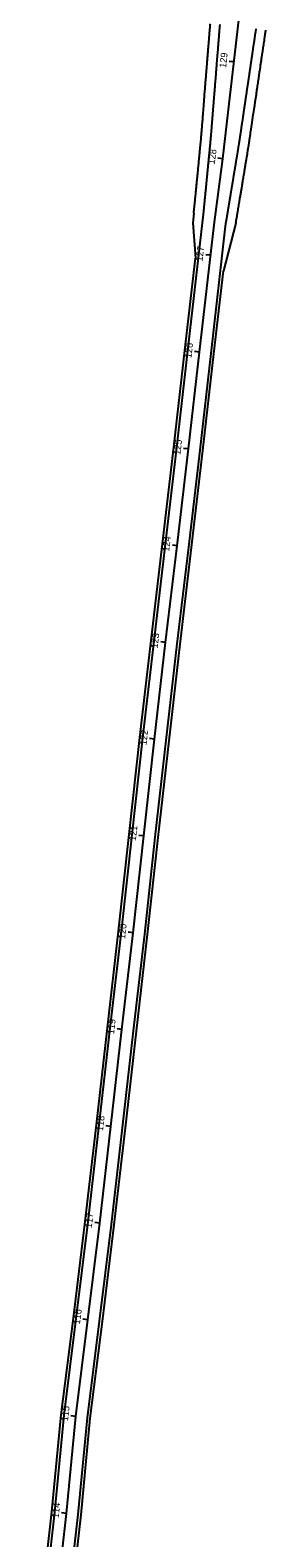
# Model space of a CAD drawing. Extents: x 2318076 to 2324211, y 613525 to 629939.
# Drawn here: x 2320288 to 2320529, y 625960 to 627508 of the extents above; entities that cross this region are included whole.
import ezdxf

# ---------------------------------------------------------------- set-up
doc = ezdxf.new("R2010")
doc.units = 0
for name, color, linetype in [('GE_P_CL_50', 7, 'Continuous'), ('PV_P_EOP', 7, 'Continuous'), ('PV_P_Shoulder', 7, 'Continuous')]:
    doc.layers.add(name, color=color, linetype=linetype)

msp = doc.modelspace()

# ---------------------------------------------------------------- linework, layer by layer
at = {"layer": 'GE_P_CL_50'}
for p, q in [((2320496.9, 627474.9), (2320491.9, 627475.5)), ((2320485.2, 627375.6), (2320480.3, 627376.2)), ((2320472.7, 627276.4), (2320467.7, 627276.9)), ((2320461.2, 627177), (2320456.3, 627177.6)), ((2320450, 627077.6), (2320445.1, 627078.2)), ((2320438.4, 626978.3), (2320433.5, 626978.9)), ((2320426.6, 626879), (2320421.7, 626879.6)), ((2320415.2, 626779.7), (2320410.2, 626780.2)), ((2320404.1, 626680.3), (2320399.2, 626680.9)), ((2320393.2, 626580.9), (2320388.2, 626581.4)), ((2320381.8, 626481.6), (2320376.8, 626482.2)), ((2320370.4, 626382.2), (2320365.4, 626382.8)), ((2320359, 626282.9), (2320354, 626283.4)), ((2320346.8, 626183.6), (2320341.8, 626184.2)), ((2320334.4, 626084.4), (2320329.5, 626085)), ((2320324.8, 625984.9), (2320319.9, 625985.4))]:
    msp.add_line(p, q, dxfattribs=at)
msp.add_lwpolyline([(2320302.5, 625786.1), (2320324.8, 625984.9), (2320334.4, 626084.4), (2320346.8, 626183.6), (2320359, 626282.9), (2320370.4, 626382.2), (2320381.8, 626481.6), (2320393.2, 626580.9), (2320404.1, 626680.3), (2320415.2, 626779.7), (2320426.6, 626879), (2320438.4, 626978.3), (2320450, 627077.6), (2320461.2, 627177), (2320476.3, 627307.7), (2320485.2, 627375.6), (2320502.1, 627520.9)], dxfattribs=at)
at = {"layer": 'PV_P_EOP'}
for points in [[(2320290.6, 625787.5), (2320312.9, 625986.1), (2320322.5, 626085.7), (2320334.9, 626185.1), (2320347, 626284.3), (2320358.5, 626383.6), (2320369.8, 626482.9), (2320381.3, 626582.2), (2320392.2, 626681.6), (2320403.3, 626781), (2320414.7, 626880.4), (2320426.5, 626979.7), (2320438.1, 627079), (2320449.3, 627178.4), (2320465.5, 627318.7)], [(2320314.4, 625784.8), (2320336.8, 625983.6), (2320346.4, 626083.1), (2320358.7, 626182.1), (2320370.9, 626281.4), (2320382.3, 626380.8), (2320393.7, 626480.2), (2320405.1, 626579.6), (2320416, 626679), (2320427.1, 626778.3), (2320438.5, 626877.6), (2320450.3, 626976.9), (2320462, 627076.3), (2320473.2, 627175.7), (2320488.2, 627306.2), (2320488.8, 627311)]]:
    msp.add_lwpolyline(points, dxfattribs=at)
for points in [[(2320477.1, 627446.7), (2320477.2, 627447.6), (2320477.3, 627448.5), (2320477.3, 627449.4), (2320477.4, 627450.3), (2320477.5, 627451.2), (2320477.5, 627452.1), (2320477.6, 627453), (2320477.7, 627453.9), (2320477.8, 627454.8), (2320477.8, 627455.7), (2320477.9, 627456.6), (2320478, 627457.5), (2320478, 627458.4), (2320478.1, 627459.3), (2320478.2, 627460.2), (2320478.3, 627461.1), (2320478.3, 627462), (2320478.4, 627462.9), (2320478.5, 627463.8), (2320478.5, 627464.7), (2320478.6, 627465.6), (2320478.7, 627466.5), (2320478.8, 627467.4), (2320478.8, 627468.3), (2320478.9, 627469.2), (2320479, 627470.1), (2320479.1, 627471), (2320479.1, 627471.9), (2320479.2, 627472.8), (2320479.3, 627473.7), (2320479.3, 627474.6), (2320479.4, 627475.5), (2320479.5, 627476.4), (2320479.6, 627477.3), (2320479.6, 627478.2), (2320479.7, 627479.1), (2320479.8, 627480), (2320479.8, 627480.9), (2320479.9, 627481.8), (2320480, 627482.7), (2320480.1, 627483.6), (2320480.1, 627484.5), (2320480.2, 627485.4), (2320480.3, 627486.3), (2320480.4, 627487.2), (2320480.4, 627488.1), (2320480.5, 627489), (2320480.6, 627489.9), (2320480.6, 627490.8), (2320480.7, 627491.7), (2320480.8, 627492.6), (2320480.9, 627493.5), (2320480.9, 627494.4), (2320481, 627495.3), (2320481.1, 627496.2), (2320481.1, 627497.1), (2320481.2, 627498), (2320481.3, 627498.9), (2320481.4, 627499.7), (2320481.4, 627500.6), (2320481.5, 627501.5), (2320481.6, 627502.4), (2320481.6, 627503.3), (2320481.7, 627504.2), (2320481.8, 627505.1), (2320481.9, 627506), (2320481.9, 627506.9), (2320482, 627507.8), (2320482.1, 627508.7), (2320482.2, 627509.6), (2320482.2, 627510.5), (2320482.3, 627511.4), (2320482.4, 627512.3), (2320482.4, 627513.2)], [(2320509.8, 627443), (2320509.9, 627443.9), (2320510, 627444.8), (2320510.2, 627445.7), (2320510.3, 627446.6), (2320510.4, 627447.5), (2320510.6, 627448.4), (2320510.7, 627449.3), (2320510.8, 627450.1), (2320511, 627451), (2320511.1, 627451.9), (2320511.2, 627452.8), (2320511.4, 627453.7), (2320511.5, 627454.6), (2320511.6, 627455.5), (2320511.8, 627456.4), (2320511.9, 627457.3), (2320512, 627458.2), (2320512.2, 627459.1), (2320512.3, 627460), (2320512.4, 627460.8), (2320512.6, 627461.7), (2320512.7, 627462.6), (2320512.8, 627463.5), (2320512.9, 627464.4), (2320513.1, 627465.3), (2320513.2, 627466.2), (2320513.3, 627467.1), (2320513.5, 627468), (2320513.6, 627468.9), (2320513.7, 627469.8), (2320513.9, 627470.7), (2320514, 627471.5), (2320514.1, 627472.4), (2320514.3, 627473.3), (2320514.4, 627474.2), (2320514.5, 627475.1), (2320514.7, 627476), (2320514.8, 627476.9), (2320514.9, 627477.8), (2320515.1, 627478.7), (2320515.2, 627479.6), (2320515.3, 627480.5), (2320515.5, 627481.4), (2320515.6, 627482.2), (2320515.7, 627483.1), (2320515.8, 627484), (2320516, 627484.9), (2320516.1, 627485.8), (2320516.2, 627486.7), (2320516.4, 627487.6), (2320516.5, 627488.5), (2320516.6, 627489.4), (2320516.8, 627490.3), (2320516.9, 627491.2), (2320517, 627492.1), (2320517.2, 627493), (2320517.3, 627493.8), (2320517.4, 627494.7), (2320517.6, 627495.6), (2320517.7, 627496.5), (2320517.8, 627497.4), (2320518, 627498.3), (2320518.1, 627499.2), (2320518.2, 627500.1), (2320518.4, 627501), (2320518.5, 627501.9), (2320518.6, 627502.8), (2320518.7, 627503.7), (2320518.9, 627504.5), (2320519, 627505.4), (2320519.1, 627506.3), (2320519.3, 627507.2), (2320519.4, 627508.1), (2320519.5, 627509)], [(2320471.5, 627380.5), (2320471.6, 627381.4), (2320471.7, 627382.3), (2320471.8, 627383.2), (2320471.9, 627384.1), (2320472, 627385), (2320472.1, 627385.9), (2320472.1, 627386.8), (2320472.2, 627387.7), (2320472.3, 627388.6), (2320472.4, 627389.5), (2320472.5, 627390.4), (2320472.6, 627391.3), (2320472.7, 627392.2), (2320472.8, 627393.1), (2320472.8, 627394), (2320472.9, 627394.9), (2320473, 627395.8), (2320473.1, 627396.4), (2320473.1, 627397.3), (2320473.2, 627398.2), (2320473.3, 627399.1), (2320473.4, 627400), (2320473.4, 627400.9), (2320473.5, 627401.8), (2320473.6, 627402.7), (2320473.6, 627403.6), (2320473.7, 627404.5), (2320473.8, 627405.4), (2320473.9, 627406.3), (2320473.9, 627407.2), (2320474, 627408.1), (2320474.1, 627409), (2320474.1, 627409.9), (2320474.2, 627410.8), (2320474.3, 627411.7), (2320474.4, 627412.6), (2320474.4, 627413.5), (2320474.5, 627414.4), (2320474.6, 627415.3), (2320474.7, 627416.2), (2320474.7, 627417.1), (2320474.8, 627418), (2320474.9, 627418.9), (2320474.9, 627419.8), (2320475, 627420.7), (2320475.1, 627421.6), (2320475.2, 627422.5), (2320475.2, 627423.4), (2320475.3, 627424.3), (2320475.4, 627425.2), (2320475.4, 627426.1), (2320475.5, 627427), (2320475.6, 627427.9), (2320475.7, 627428.8), (2320475.7, 627429.7), (2320475.8, 627430.6), (2320475.9, 627431.5), (2320476, 627432.4), (2320476, 627433.3), (2320476.1, 627434.2), (2320476.2, 627435.1), (2320476.2, 627436), (2320476.3, 627436.9), (2320476.4, 627437.8), (2320476.5, 627438.6), (2320476.5, 627439.5), (2320476.6, 627440.4), (2320476.7, 627441.3), (2320476.7, 627442.2), (2320476.8, 627443.1), (2320476.9, 627444), (2320477, 627444.9), (2320477, 627445.8), (2320477.1, 627446.7)], [(2320499.7, 627376.8), (2320499.9, 627377.7), (2320500, 627378.6), (2320500.2, 627379.5), (2320500.3, 627380.4), (2320500.5, 627381.3), (2320500.6, 627382.2), (2320500.8, 627383), (2320500.9, 627383.9), (2320501.1, 627384.8), (2320501.2, 627385.7), (2320501.3, 627386.6), (2320501.5, 627387.5), (2320501.6, 627388.4), (2320501.8, 627389.3), (2320501.9, 627390.2), (2320502.1, 627391), (2320502.2, 627391.9), (2320502.4, 627393.1), (2320502.5, 627394), (2320502.7, 627394.9), (2320502.8, 627395.8), (2320502.9, 627396.6), (2320503.1, 627397.5), (2320503.2, 627398.4), (2320503.3, 627399.3), (2320503.5, 627400.2), (2320503.6, 627401.1), (2320503.7, 627402), (2320503.9, 627402.9), (2320504, 627403.8), (2320504.1, 627404.7), (2320504.2, 627405.6), (2320504.4, 627406.5), (2320504.5, 627407.3), (2320504.6, 627408.2), (2320504.8, 627409.1), (2320504.9, 627410), (2320505, 627410.9), (2320505.2, 627411.8), (2320505.3, 627412.7), (2320505.4, 627413.6), (2320505.6, 627414.5), (2320505.7, 627415.4), (2320505.8, 627416.3), (2320506, 627417.2), (2320506.1, 627418), (2320506.2, 627418.9), (2320506.4, 627419.8), (2320506.5, 627420.7), (2320506.6, 627421.6), (2320506.8, 627422.5), (2320506.9, 627423.4), (2320507, 627424.3), (2320507.1, 627425.2), (2320507.3, 627426.1), (2320507.4, 627427), (2320507.5, 627427.9), (2320507.7, 627428.7), (2320507.8, 627429.6), (2320507.9, 627430.5), (2320508.1, 627431.4), (2320508.2, 627432.3), (2320508.3, 627433.2), (2320508.5, 627434.1), (2320508.6, 627435), (2320508.7, 627435.9), (2320508.9, 627436.8), (2320509, 627437.7), (2320509.1, 627438.6), (2320509.3, 627439.4), (2320509.4, 627440.3), (2320509.5, 627441.2), (2320509.7, 627442.1), (2320509.8, 627443)]]:
    msp.add_spline(points, degree=3, dxfattribs=at)
for points in [[(2320465.5, 627318.7), (2320465.5, 627319), (2320465.5, 627319.3), (2320465.6, 627319.5), (2320465.6, 627319.8), (2320465.6, 627320.1), (2320465.7, 627320.4), (2320465.7, 627320.7), (2320465.7, 627321), (2320465.7, 627321.3), (2320465.8, 627321.6), (2320465.8, 627321.9), (2320465.8, 627322.2), (2320465.9, 627322.5), (2320465.9, 627322.8), (2320465.9, 627323.1), (2320465.9, 627323.4), (2320466, 627323.7), (2320466, 627324), (2320466, 627324.3), (2320466.1, 627324.6), (2320466.1, 627324.9), (2320466.1, 627325.2), (2320466.2, 627325.5), (2320466.2, 627325.8), (2320466.2, 627326.1), (2320466.2, 627326.4), (2320466.3, 627326.7), (2320466.3, 627327), (2320466.3, 627327.3), (2320466.4, 627327.6), (2320466.4, 627327.9), (2320466.4, 627328.2), (2320466.4, 627328.5), (2320466.5, 627328.8), (2320466.5, 627329.1), (2320466.5, 627329.4), (2320466.6, 627329.7), (2320466.6, 627330), (2320466.6, 627330.3), (2320466.6, 627330.6), (2320466.7, 627330.9), (2320466.7, 627331.2), (2320466.7, 627331.5), (2320466.8, 627331.8), (2320466.8, 627332.1), (2320466.8, 627332.4), (2320466.9, 627332.7), (2320466.9, 627333), (2320466.9, 627333.3), (2320466.9, 627333.6), (2320467, 627333.9), (2320467, 627334.2), (2320467, 627334.5), (2320467.1, 627334.8), (2320467.1, 627335.1), (2320467.1, 627335.4), (2320467.1, 627335.7), (2320467.2, 627336), (2320467.2, 627336.3), (2320467.2, 627336.6), (2320467.3, 627336.9), (2320467.3, 627337.2), (2320467.3, 627337.5), (2320467.4, 627337.8), (2320467.4, 627338.1), (2320467.4, 627338.4), (2320467.4, 627338.7), (2320467.5, 627339), (2320467.5, 627339.3), (2320467.5, 627339.6), (2320467.6, 627339.9), (2320467.6, 627340.2), (2320467.6, 627340.5), (2320467.6, 627340.8), (2320467.7, 627341.1), (2320467.7, 627341.3), (2320467.7, 627341.6), (2320467.8, 627341.9), (2320467.8, 627342.2), (2320467.8, 627342.5), (2320467.8, 627342.8), (2320467.9, 627343.1), (2320467.9, 627343.4), (2320467.9, 627343.7), (2320468, 627344), (2320468, 627344.3), (2320468, 627344.6), (2320468.1, 627344.9), (2320468.1, 627345.2), (2320468.1, 627345.5), (2320468.1, 627345.8), (2320468.2, 627346.1), (2320468.2, 627346.4), (2320468.2, 627346.7), (2320468.3, 627347), (2320468.3, 627347.3), (2320468.3, 627347.6), (2320468.3, 627347.9), (2320468.4, 627348.2), (2320468.4, 627348.5), (2320468.4, 627348.8), (2320468.5, 627349.1), (2320468.5, 627349.4), (2320468.5, 627349.7), (2320468.5, 627350), (2320468.6, 627350.3), (2320468.6, 627350.6), (2320468.6, 627350.9), (2320468.7, 627351.2), (2320468.7, 627351.5), (2320468.7, 627351.8), (2320468.8, 627352.1), (2320468.8, 627352.4), (2320468.8, 627352.7), (2320468.8, 627353), (2320468.9, 627353.3), (2320468.9, 627353.6), (2320468.9, 627353.9), (2320469, 627354.2), (2320469, 627354.5), (2320469, 627354.8), (2320469, 627355.1), (2320469.1, 627355.4), (2320469.1, 627355.7), (2320469.1, 627356), (2320469.2, 627356.3), (2320469.2, 627356.6), (2320469.2, 627356.9), (2320469.2, 627357.2), (2320469.3, 627357.5), (2320469.3, 627357.8), (2320469.3, 627358.1), (2320469.4, 627358.4), (2320469.4, 627358.7), (2320469.4, 627359), (2320469.5, 627359.3), (2320469.5, 627359.6), (2320469.5, 627359.9), (2320469.5, 627360.2), (2320469.6, 627360.5), (2320469.6, 627360.8), (2320469.6, 627361.1), (2320469.7, 627361.4), (2320469.7, 627361.7), (2320469.7, 627362), (2320469.7, 627362.3), (2320469.8, 627362.6), (2320469.8, 627362.9), (2320469.8, 627363.2), (2320469.9, 627363.5), (2320469.9, 627363.8), (2320469.9, 627364.1), (2320470, 627364.4), (2320470, 627364.7), (2320470, 627365), (2320470, 627365.3), (2320470.1, 627365.6), (2320470.1, 627365.9), (2320470.1, 627366.2), (2320470.2, 627366.5), (2320470.2, 627366.8), (2320470.2, 627367.1), (2320470.2, 627367.4), (2320470.3, 627367.7), (2320470.3, 627368), (2320470.3, 627368.3), (2320470.4, 627368.6), (2320470.4, 627368.9), (2320470.4, 627369.2), (2320470.4, 627369.5), (2320470.5, 627369.8), (2320470.5, 627370.1), (2320470.5, 627370.4), (2320470.6, 627370.7), (2320470.6, 627371), (2320470.6, 627371.3), (2320470.7, 627371.6), (2320470.7, 627371.9), (2320470.7, 627372.2), (2320470.7, 627372.4), (2320470.8, 627372.7), (2320470.8, 627373), (2320470.8, 627373.3), (2320470.9, 627373.6), (2320470.9, 627373.9), (2320470.9, 627374.2), (2320470.9, 627374.5), (2320471, 627374.8), (2320471, 627375.1), (2320471, 627375.4), (2320471.1, 627375.7), (2320471.1, 627376), (2320471.1, 627376.3), (2320471.1, 627376.6), (2320471.2, 627376.9), (2320471.2, 627377.2), (2320471.2, 627377.5), (2320471.3, 627377.8), (2320471.3, 627378.1), (2320471.3, 627378.4), (2320471.4, 627378.7), (2320471.4, 627379), (2320471.4, 627379.3), (2320471.4, 627379.6), (2320471.5, 627379.9), (2320471.5, 627380.2), (2320471.5, 627380.5)], [(2320488.8, 627311), (2320488.9, 627311.3), (2320488.9, 627311.6), (2320489, 627311.9), (2320489, 627312.2), (2320489.1, 627312.5), (2320489.1, 627312.8), (2320489.2, 627313.1), (2320489.2, 627313.4), (2320489.3, 627313.7), (2320489.3, 627314), (2320489.4, 627314.3), (2320489.4, 627314.6), (2320489.5, 627314.9), (2320489.5, 627315.2), (2320489.6, 627315.5), (2320489.6, 627315.8), (2320489.7, 627316), (2320489.7, 627316.3), (2320489.8, 627316.6), (2320489.8, 627316.9), (2320489.9, 627317.2), (2320489.9, 627317.5), (2320490, 627317.8), (2320490, 627318.1), (2320490.1, 627318.4), (2320490.1, 627318.7), (2320490.2, 627319), (2320490.2, 627319.3), (2320490.3, 627319.6), (2320490.3, 627319.9), (2320490.4, 627320.2), (2320490.4, 627320.5), (2320490.5, 627320.8), (2320490.5, 627321.1), (2320490.6, 627321.4), (2320490.6, 627321.7), (2320490.7, 627322), (2320490.7, 627322.3), (2320490.8, 627322.6), (2320490.8, 627322.9), (2320490.8, 627323.2), (2320490.9, 627323.5), (2320490.9, 627323.8), (2320491, 627324.1), (2320491, 627324.3), (2320491.1, 627324.6), (2320491.1, 627324.9), (2320491.2, 627325.2), (2320491.2, 627325.5), (2320491.3, 627325.8), (2320491.3, 627326.1), (2320491.4, 627326.4), (2320491.4, 627326.7), (2320491.5, 627327), (2320491.5, 627327.3), (2320491.6, 627327.6), (2320491.6, 627327.9), (2320491.7, 627328.2), (2320491.7, 627328.5), (2320491.8, 627328.8), (2320491.8, 627329.1), (2320491.9, 627329.4), (2320491.9, 627329.7), (2320492, 627330), (2320492, 627330.3), (2320492.1, 627330.6), (2320492.1, 627330.9), (2320492.2, 627331.2), (2320492.2, 627331.5), (2320492.3, 627331.8), (2320492.3, 627332.1), (2320492.4, 627332.4), (2320492.4, 627332.6), (2320492.5, 627332.9), (2320492.5, 627333.2), (2320492.6, 627333.5), (2320492.6, 627333.8), (2320492.7, 627334.1), (2320492.7, 627334.4), (2320492.8, 627334.7), (2320492.8, 627335), (2320492.9, 627335.3), (2320492.9, 627335.6), (2320493, 627335.9), (2320493, 627336.2), (2320493.1, 627336.5), (2320493.1, 627336.8), (2320493.2, 627337.1), (2320493.2, 627337.4), (2320493.3, 627337.7), (2320493.3, 627338), (2320493.4, 627338.3), (2320493.4, 627338.6), (2320493.4, 627338.9), (2320493.5, 627339.2), (2320493.5, 627339.5), (2320493.6, 627339.8), (2320493.6, 627340.1), (2320493.7, 627340.4), (2320493.7, 627340.7), (2320493.8, 627340.9), (2320493.8, 627341.2), (2320493.9, 627341.5), (2320493.9, 627341.8), (2320494, 627342.1), (2320494, 627342.4), (2320494.1, 627342.7), (2320494.1, 627343), (2320494.2, 627343.3), (2320494.2, 627343.6), (2320494.3, 627343.9), (2320494.3, 627344.2), (2320494.4, 627344.5), (2320494.4, 627344.8), (2320494.5, 627345.1), (2320494.5, 627345.4), (2320494.6, 627345.7), (2320494.6, 627346), (2320494.7, 627346.3), (2320494.7, 627346.6), (2320494.8, 627346.9), (2320494.8, 627347.2), (2320494.9, 627347.5), (2320494.9, 627347.8), (2320495, 627348.1), (2320495, 627348.4), (2320495.1, 627348.7), (2320495.1, 627349), (2320495.2, 627349.2), (2320495.2, 627349.5), (2320495.3, 627349.8), (2320495.3, 627350.1), (2320495.4, 627350.4), (2320495.4, 627350.7), (2320495.5, 627351), (2320495.5, 627351.3), (2320495.6, 627351.6), (2320495.6, 627351.9), (2320495.7, 627352.2), (2320495.7, 627352.5), (2320495.8, 627352.8), (2320495.8, 627353.1), (2320495.9, 627353.4), (2320495.9, 627353.7), (2320496, 627354), (2320496, 627354.3), (2320496.1, 627354.6), (2320496.1, 627354.9), (2320496.1, 627355.2), (2320496.2, 627355.5), (2320496.2, 627355.8), (2320496.3, 627356.1), (2320496.3, 627356.4), (2320496.4, 627356.7), (2320496.4, 627357), (2320496.5, 627357.3), (2320496.5, 627357.5), (2320496.6, 627357.8), (2320496.6, 627358.1), (2320496.7, 627358.4), (2320496.7, 627358.7), (2320496.8, 627359), (2320496.8, 627359.3), (2320496.9, 627359.6), (2320496.9, 627359.9), (2320497, 627360.2), (2320497, 627360.5), (2320497.1, 627360.8), (2320497.1, 627361.1), (2320497.2, 627361.4), (2320497.2, 627361.7), (2320497.3, 627362), (2320497.3, 627362.3), (2320497.4, 627362.6), (2320497.4, 627362.9), (2320497.5, 627363.2), (2320497.5, 627363.5), (2320497.6, 627363.8), (2320497.6, 627364.1), (2320497.7, 627364.4), (2320497.7, 627364.7), (2320497.8, 627365), (2320497.8, 627365.3), (2320497.9, 627365.6), (2320497.9, 627365.8), (2320498, 627366.1), (2320498, 627366.4), (2320498.1, 627366.7), (2320498.1, 627367), (2320498.2, 627367.3), (2320498.2, 627367.6), (2320498.3, 627367.9), (2320498.3, 627368.2), (2320498.4, 627368.5), (2320498.4, 627368.8), (2320498.5, 627369.1), (2320498.5, 627369.4), (2320498.6, 627369.7), (2320498.6, 627370), (2320498.7, 627370.3), (2320498.7, 627370.6), (2320498.7, 627370.9), (2320498.8, 627371.2), (2320498.8, 627371.5), (2320498.9, 627371.8), (2320498.9, 627372.1), (2320499, 627372.4), (2320499, 627372.7), (2320499.1, 627373), (2320499.1, 627373.3), (2320499.2, 627373.6), (2320499.2, 627373.9), (2320499.3, 627374.1), (2320499.3, 627374.4), (2320499.4, 627374.7), (2320499.4, 627375), (2320499.5, 627375.3), (2320499.5, 627375.6), (2320499.6, 627375.9), (2320499.6, 627376.2), (2320499.7, 627376.5), (2320499.7, 627376.8)]]:
    msp.add_open_spline(points, degree=3, dxfattribs=at)
at = {"layer": 'PV_P_Shoulder'}
for p, q in [((2320455.5, 627319.7), (2320454.4, 627309.8)), ((2320454.4, 627309.8), (2320457.3, 627273.5)), ((2320498.7, 627309.4), (2320485.9, 627260.4))]:
    msp.add_line(p, q, dxfattribs=at)
for points in [[(2320287.6, 625787.8), (2320309.9, 625986.4), (2320319.5, 626086), (2320331.9, 626185.4), (2320344.1, 626284.6), (2320355.5, 626383.9), (2320366.9, 626483.3), (2320378.3, 626582.6), (2320389.2, 626681.9), (2320400.3, 626781.4), (2320411.7, 626880.8), (2320423.5, 626980.1), (2320435.1, 627079.4), (2320446.3, 627178.7), (2320457.3, 627273.5)], [(2320317.4, 625784.5), (2320339.8, 625983.3), (2320349.3, 626082.7), (2320361.7, 626181.8), (2320373.8, 626281.1), (2320385.3, 626380.5), (2320396.7, 626479.8), (2320408.1, 626579.2), (2320419, 626678.6), (2320430.1, 626778), (2320441.5, 626877.3), (2320453.3, 626976.6), (2320464.9, 627075.9), (2320476.1, 627175.3), (2320485.9, 627260.4)]]:
    msp.add_lwpolyline(points, dxfattribs=at)
for points, degree in [([(2320467.1, 627447.5), (2320468.9, 627469.7), (2320470.7, 627491.9), (2320472.5, 627514)], 2), ([(2320519.7, 627441.6), (2320522.9, 627463.5), (2320526.2, 627485.5), (2320529.4, 627507.5)], 2), ([(2320463.1, 627396.7), (2320463.1, 627396.8), (2320463.1, 627396.9), (2320463.1, 627397.1), (2320463.1, 627397.1), (2320463.1, 627397.2), (2320463.1, 627397.2), (2320463.1, 627397.2), (2320463.1, 627397.2), (2320463.1, 627397.2), (2320463.1, 627397.2), (2320463.1, 627397.3), (2320463.1, 627397.4), (2320463.1, 627397.7), (2320463.2, 627398.6), (2320463.4, 627400.4), (2320463.7, 627404.1), (2320464.3, 627411.6), (2320465.4, 627426.4), (2320466.5, 627439.1), (2320467.1, 627447.5)], 3), ([(2320509.6, 627375.2), (2320510.1, 627377.9), (2320510.7, 627382.1), (2320511.5, 627386.9), (2320511.9, 627389.1), (2320512.1, 627390), (2320512.1, 627390.2), (2320512.1, 627390.3), (2320512.1, 627390.3), (2320512.1, 627390.3), (2320512.1, 627390.3), (2320512.1, 627390.3), (2320512.1, 627390.4), (2320512.1, 627390.6), (2320512.2, 627390.7), (2320512.2, 627391), (2320512.2, 627391.2), (2320512.3, 627391.5), (2320512.3, 627391.5), (2320512.3, 627391.6), (2320512.3, 627391.6), (2320512.3, 627391.6), (2320512.3, 627391.7), (2320512.3, 627391.7), (2320512.3, 627391.8), (2320513.1, 627397.3), (2320515.6, 627414), (2320518, 627430.5), (2320519.7, 627441.6)], 3), ([(2320461.6, 627381.5), (2320462.1, 627386.6), (2320462.6, 627391.7), (2320463.1, 627396.7)], 2), ([(2320455.5, 627319.7), (2320457.6, 627340.3), (2320459.6, 627360.9), (2320461.6, 627381.5)], 2), ([(2320498.7, 627309.4), (2320502.3, 627331.3), (2320506, 627353.2), (2320509.6, 627375.2)], 2)]:
    msp.add_open_spline(points, degree=degree, dxfattribs=at)

# ---------------------------------------------------------------- texts
at = {"layer": 'GE_P_CL_50'}
for s, rotation, p in [('129', 83.502, (2320488.6, 627468.5)), ('128', 82.5115, (2320476.9, 627369.4)), ('127', 83.4266, (2320464.4, 627269.8)), ('126', 83.4266, (2320453, 627170.6)), ('125', 83.2425, (2320441.7, 627071.3)), ('124', 83.4147, (2320430.2, 626972)), ('123', 83.1535, (2320418.3, 626872.6)), ('122', 83.7156, (2320406.9, 626773.3)), ('121', 83.6069, (2320396, 626675.1)), ('120', 83.8237, (2320385, 626574.3)), ('119', 83.1351, (2320373.6, 626476.5)), ('118', 83.6032, (2320362.3, 626377.2)), ('117', 83.3517, (2320350.8, 626277.6)), ('116', 82.6527, (2320338.6, 626178.6)), ('115', 83.1126, (2320326.3, 626079.3)), ('114', 83.2927, (2320316.7, 625979.9))]:
    msp.add_text(s, height=7, rotation=rotation, dxfattribs=at).set_placement(p)

doc.saveas('drawing.dxf')
